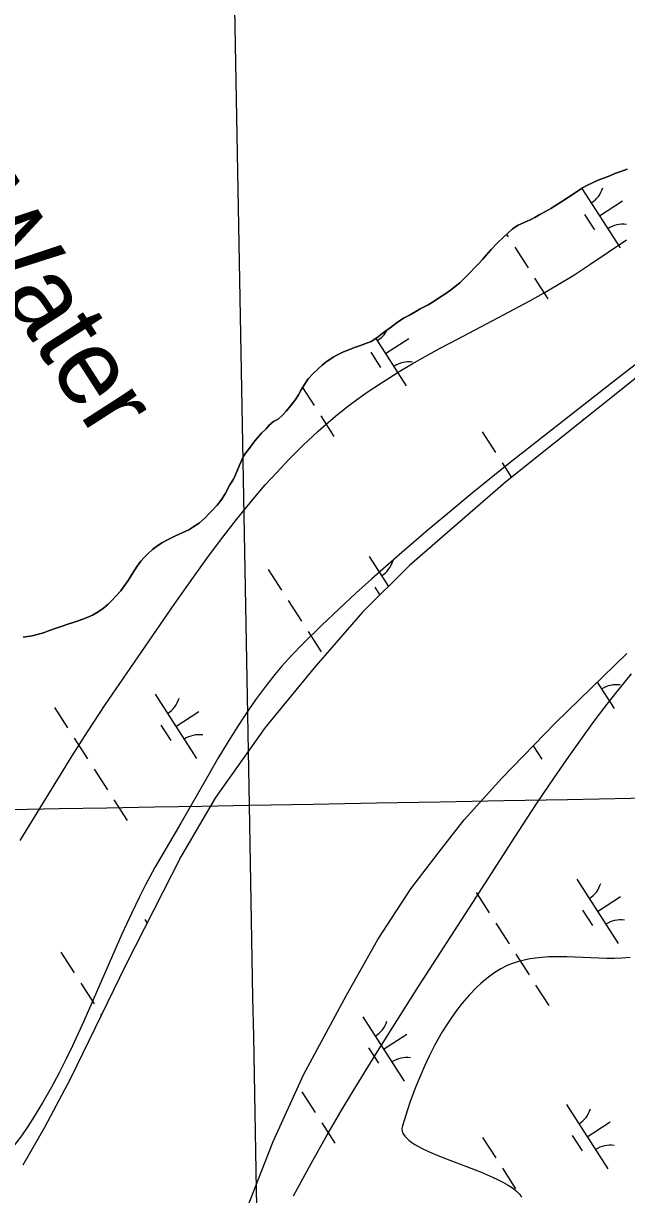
# Model space of a CAD drawing. Extents: x 3937982 to 3958556, y 219448 to 241894.
# Drawn here: x 3945931 to 3946325, y 230060 to 230826 of the extents above; entities that cross this region are included whole.
import ezdxf

# ---------------------------------------------------------------- set-up
doc = ezdxf.new("R2010")
doc.units = 0
for name, color, linetype in [('V-GRID-MAJR', 7, 'Continuous'), ('V-RIVR-IDEN', 7, 'Continuous'), ('V-SITE-VEGE', 7, 'Continuous'), ('V-TOPO-SHOR', 7, 'Continuous'), ('V-WETL-SWMP', 7, 'Continuous')]:
    doc.layers.add(name, color=color, linetype=linetype)

msp = doc.modelspace()

# ---------------------------------------------------------------- linework, layer by layer
at = {"layer": 'V-GRID-MAJR'}
for points in [[(3946136.867, 227095.12), (3946078.329, 230314.506), (3945968.142, 236374.431), (3945930.73, 238431.955)], [(3944087.88, 230278.368), (3946078.329, 230314.506), (3951399.696, 230411.652), (3955204.154, 230481.575)]]:
    msp.add_spline(points, degree=3, dxfattribs=at)
at = {"layer": 'V-SITE-VEGE'}
for p, q in [((3946316.959, 230386.607), (3946328.088, 230400.386)), ((3946310.758, 230378.632), (3946316.959, 230386.607)), ((3946303.803, 230369.436), (3946310.758, 230378.632)), ((3946296.004, 230358.826), (3946303.803, 230369.436)), ((3946287.274, 230346.583), (3946296.004, 230358.826)), ((3946277.496, 230332.449), (3946287.274, 230346.583)), ((3946266.54, 230316.145), (3946277.496, 230332.449)), ((3946254.223, 230297.351), (3946266.54, 230316.145)), ((3946224.457, 230250.88), (3946254.223, 230297.351)), ((3946188.933, 230195.922), (3946224.457, 230250.88)), ((3946246.822, 230209.629), (3946242.674, 230207.552)), ((3946249.654, 230210.798), (3946246.822, 230209.629)), ((3946253.504, 230212.113), (3946249.654, 230210.798)), ((3946258.759, 230213.467), (3946253.504, 230212.113)), ((3946261.819, 230214.057), (3946258.759, 230213.467)), ((3946265.354, 230214.581), (3946261.819, 230214.057)), ((3946269.442, 230215.011), (3946265.354, 230214.581)), ((3946274.164, 230215.3), (3946269.442, 230215.011)), ((3946279.61, 230215.421), (3946274.164, 230215.3)), ((3946285.871, 230215.347), (3946279.61, 230215.421)), ((3946311.891, 230214.327), (3946285.871, 230215.347)), ((3946316.771, 230214.319), (3946311.891, 230214.327)), ((3946321.879, 230214.491), (3946316.771, 230214.319)), ((3946327.185, 230214.939), (3946321.879, 230214.491)), ((3946232.4, 230200.321), (3946229.549, 230197.861)), ((3946235.433, 230202.727), (3946232.4, 230200.321)), ((3946238.66, 230205.06), (3946235.433, 230202.727)), ((3946242.674, 230207.552), (3946238.66, 230205.06)), ((3946171.986, 230169.435), (3946188.933, 230195.922)), ((3946226.866, 230195.373), (3946221.891, 230190.263)), ((3946229.549, 230197.861), (3946226.866, 230195.373)), ((3946217.492, 230185.172), (3946213.595, 230180.181)), ((3946221.891, 230190.263), (3946217.492, 230185.172)), ((3946213.595, 230180.181), (3946210.132, 230175.335)), ((3946207.053, 230170.682), (3946204.311, 230166.242)), ((3946210.132, 230175.335), (3946207.053, 230170.682)), ((3946160.869, 230151.732), (3946171.986, 230169.435)), ((3946204.311, 230166.242), (3946199.539, 230157.792)), ((3946199.539, 230157.792), (3946195.748, 230150.352)), ((3946146.31, 230127.983), (3946160.869, 230151.732)), ((3946195.748, 230150.352), (3946192.715, 230143.882)), ((3946192.715, 230143.882), (3946190.272, 230138.303)), ((3946190.272, 230138.303), (3946186.684, 230129.431)), ((3946138.134, 230114.301), (3946146.31, 230127.983)), ((3946186.684, 230129.431), (3946183.243, 230120.078)), ((3946183.243, 230120.078), (3946181.814, 230115.912)), ((3946128.93, 230098.527), (3946138.134, 230114.301)), ((3946181.814, 230115.912), (3946178.31, 230104.923)), ((3946178.099, 230103.999), (3946178.021, 230103.104)), ((3946178.021, 230103.104), (3946178.236, 230101.376)), ((3946178.31, 230104.923), (3946178.099, 230103.999)), ((3946178.236, 230101.376), (3946178.883, 230099.739)), ((3946118.609, 230080.287), (3946128.93, 230098.527)), ((3946178.883, 230099.739), (3946179.897, 230098.191)), ((3946179.897, 230098.191), (3946181.212, 230096.721)), ((3946181.212, 230096.721), (3946182.779, 230095.324)), ((3946182.779, 230095.324), (3946184.552, 230093.991)), ((3946184.552, 230093.991), (3946186.489, 230092.719)), ((3946186.489, 230092.719), (3946190.725, 230090.339)), ((3946190.725, 230090.339), (3946195.32, 230088.117)), ((3946195.32, 230088.117), (3946200.031, 230086.067)), ((3946200.031, 230086.067), (3946204.719, 230084.158)), ((3946107.084, 230059.105), (3946118.609, 230080.287)), ((3946204.719, 230084.158), (3946229.313, 230074.735)), ((3946229.313, 230074.735), (3946235.244, 230072.276)), ((3946235.244, 230072.276), (3946240.1, 230070.078)), ((3946240.1, 230070.078), (3946244.016, 230068.112)), ((3946244.016, 230068.112), (3946247.135, 230066.357)), ((3946247.135, 230066.357), (3946249.59, 230064.786)), ((3946249.59, 230064.786), (3946251.509, 230063.385)), ((3946251.509, 230063.385), (3946252.994, 230062.136)), ((3946252.994, 230062.136), (3946255.005, 230060.035)), ((3946255.005, 230060.035), (3946256.22, 230058.269))]:
    msp.add_line(p, q, dxfattribs=at)
for points in [[(3945928.48, 230291.467), (3945962.41, 230346.73), (3945972.347, 230362.365), (3945984.051, 230380.055), (3946029.609, 230446.302), (3946042.812, 230465.133), (3946050.492, 230475.785), (3946059.44, 230487.823), (3946069.932, 230501.366), (3946075.664, 230508.481), (3946081.896, 230515.975), (3946088.693, 230523.849), (3946096.124, 230532.105), (3946104.277, 230540.729), (3946113.253, 230549.707), (3946123.171, 230559.007), (3946128.441, 230563.689), (3946135.783, 230569.868), (3946143.295, 230575.766), (3946148.391, 230579.553), (3946155.28, 230584.44), (3946164.629, 230590.688), (3946177.337, 230598.61), (3946184.704, 230602.96), (3946193.201, 230607.799), (3946202.992, 230613.195), (3946214.26, 230619.233), (3946244.452, 230635.082), (3946261.602, 230644.305), (3946270.66, 230649.365), (3946280.231, 230654.917), (3946290.307, 230661.057), (3946300.874, 230667.908), (3946324.951, 230684.107)], [(3946375, 230636.678), (3946320.033, 230594.235), (3946283.78, 230566.071), (3946247.792, 230537.704), (3946224.025, 230518.537), (3946210.541, 230507.449), (3946195.234, 230494.635), (3946177.886, 230479.77), (3946158.272, 230462.45), (3946147.915, 230453.05), (3946136.95, 230442.89), (3946125.357, 230431.884), (3946113.112, 230419.94), (3946106.036, 230412.633), (3946099.292, 230405.082), (3946094.968, 230399.923), (3946089.396, 230392.9), (3946082.283, 230383.307), (3946078.361, 230377.723), (3946073.997, 230371.255), (3946069.139, 230363.772), (3946063.739, 230355.111), (3946057.719, 230345.104), (3946050.994, 230333.57), (3946033.338, 230302.655), (3946016.512, 230273.854), (3946010.349, 230262.359), (3946006.423, 230254.609), (3946001.381, 230244.187), (3945994.926, 230230.16), (3945970.096, 230173.394), (3945962.649, 230157.249), (3945958.502, 230148.699), (3945953.912, 230139.634)], [(3945953.912, 230139.634), (3945948.79, 230130.052), (3945943.033, 230119.933), (3945936.509, 230109.285), (3945932.968, 230103.856), (3945929.183, 230098.3), (3945925.593, 230093.468), (3945921.779, 230088.924), (3945919.119, 230086.042), (3945915.431, 230082.374), (3945910.278, 230077.768), (3945907.218, 230075.272), (3945903.628, 230072.526), (3945899.405, 230069.519), (3945894.432, 230066.238), (3945888.577, 230062.662), (3945881.682, 230058.765)]]:
    msp.add_lwpolyline(points, dxfattribs=at)
at = {"layer": 'V-TOPO-SHOR'}
for p, q in [((3946278.387, 230368.457), (3946325.008, 230413.677)), ((3946243.329, 230332.21), (3946278.387, 230368.457)), ((3946218.668, 230304.926), (3946243.329, 230332.21)), ((3946203.944, 230285.899), (3946218.668, 230304.926)), ((3946183.932, 230259.826), (3946203.944, 230285.899)), ((3946162.359, 230226.746), (3946183.932, 230259.826)), ((3946141.751, 230190.413), (3946162.359, 230226.746)), ((3946113.613, 230138.155), (3946141.751, 230190.413)), ((3946093.778, 230094.605), (3946113.613, 230138.155)), ((3946069.925, 230033.534), (3946093.778, 230094.605))]:
    msp.add_line(p, q, dxfattribs=at)
for points in [[(3946655.328, 230838.166), (3946632.511, 230813.236), (3946613.334, 230797.196), (3946587.893, 230778.299), (3946515.953, 230726.542), (3946438.459, 230670.767), (3946338.748, 230600.088), (3946245.832, 230525.75), (3946183.006, 230471.29), (3946152.325, 230440.688), (3946120.538, 230404.25), (3946088.546, 230365.246), (3946056.155, 230319.482), (3946033.707, 230281.274), (3945997.377, 230210.071), (3945961.087, 230135.375), (3945944.397, 230103.749), (3945930.199, 230079.141)], [(3946325.301, 230730.316), (3946321.059, 230728.801), (3946317.31, 230727.453), (3946313.887, 230725.944), (3946310.463, 230724.601), (3946306.222, 230723.085), (3946302.963, 230721.578), (3946298.892, 230719.573), (3946296.123, 230718.072), (3946291.247, 230714.911), (3946285.717, 230711.256), (3946280.19, 230707.598), (3946275.471, 230704.604), (3946272.381, 230702.773), (3946268.147, 230700.6), (3946264.891, 230698.767), (3946261.796, 230697.264), (3946257.887, 230695.423), (3946253.975, 230693.747), (3946250.399, 230691.255), (3946246.992, 230688.273), (3946244.397, 230685.957), (3946240.346, 230681.988), (3946236.295, 230677.855), (3946233.385, 230674.224), (3946230.796, 230671.25), (3946228.529, 230668.772), (3946225.287, 230665.628), (3946222.86, 230662.986), (3946219.133, 230659.183), (3946215.891, 230656.04), (3946212.806, 230653.553), (3946209.72, 230651.231), (3946205.98, 230648.575), (3946202.566, 230646.412), (3946198.337, 230643.586), (3946195.085, 230641.589), (3946189.875, 230638.916), (3946187.108, 230637.251), (3946183.039, 230634.919), (3946179.457, 230633.082), (3946175.879, 230630.755), (3946173.116, 230628.762), (3946170.355, 230626.608), (3946167.593, 230624.613), (3946164.832, 230622.622), (3946161.582, 230620.134), (3946158.006, 230617.642), (3946153.767, 230616.126), (3946150.832, 230614.951), (3946147.078, 230613.767), (3946143.33, 230612.255), (3946139.906, 230610.912), (3946135.832, 230608.907), (3946133.065, 230607.406), (3946128.353, 230604.084), (3946125.916, 230602.257), (3946123.157, 230599.775), (3946120.079, 230596.633), (3946116.675, 230593.326), (3946114.259, 230589.537), (3946112.166, 230586.078), (3946110.398, 230582.787), (3946108.467, 230579.655), (3946106.527, 230577.181), (3946104.588, 230574.705), (3946102.323, 230572.065), (3946099.892, 230569.585), (3946097.137, 230566.937), (3946094.043, 230565.432), (3946091.284, 230562.95), (3946089.181, 230560.638), (3946086.262, 230557.826), (3946083.35, 230554.358), (3946081.249, 230551.88), (3946078.341, 230547.924), (3946075.918, 230544.788), (3946074.144, 230542.152), (3946071.742, 230536.725), (3946069.188, 230530.481), (3946067.906, 230527.683), (3946065.488, 230524.058)], [(3946065.488, 230524.058), (3946062.438, 230518.136), (3946059.536, 230513.685), (3946057.111, 230510.716), (3946053.871, 230507.244), (3946051.768, 230504.932), (3946049.501, 230502.618), (3946045.444, 230498.974), (3946041.378, 230496.314), (3946038.616, 230494.485), (3946035.193, 230492.978), (3946032.261, 230491.638), (3946029.492, 230490.301), (3946025.255, 230488.294), (3946021.511, 230486.291), (3946018.42, 230484.296), (3946014.847, 230481.642), (3946012.09, 230478.994), (3946009.497, 230476.35), (3946007.23, 230474.036), (3946004.807, 230470.737), (3946001.426, 230465.301), (3945999.009, 230461.512), (3945996.265, 230457.556), (3945994.168, 230454.588), (3945991.256, 230451.285), (3945988.825, 230448.805), (3945985.908, 230445.829), (3945982.988, 230443.345), (3945979.41, 230441.016), (3945975.666, 230438.849), (3945972.246, 230437.178), (3945969.311, 230436.166), (3945966.213, 230434.989), (3945962.948, 230433.975), (3945959.522, 230432.957), (3945955.77, 230431.61), (3945951.856, 230430.262), (3945946.964, 230428.411), (3945943.701, 230427.233), (3945940.439, 230426.217), (3945936.193, 230425.191), (3945930.309, 230424.315)]]:
    msp.add_lwpolyline(points, dxfattribs=at)
at = {"layer": 'V-WETL-SWMP'}
for p, q in [((3946317.309, 230727.453), (3946321.06, 230728.8)), ((3946321.06, 230728.8), (3946325.301, 230730.316)), ((3946298.892, 230719.573), (3946302.964, 230721.578)), ((3946302.964, 230721.578), (3946306.222, 230723.085)), ((3946306.222, 230723.085), (3946310.463, 230724.601)), ((3946310.463, 230724.601), (3946313.887, 230725.945)), ((3946313.887, 230725.945), (3946317.309, 230727.453)), ((3946285.717, 230711.255), (3946291.246, 230714.912)), ((3946291.246, 230714.912), (3946296.124, 230718.072)), ((3946295.65, 230717.765), (3946320.729, 230678.803)), ((3946296.124, 230718.072), (3946298.892, 230719.573)), ((3946275.472, 230704.604), (3946280.189, 230707.598)), ((3946280.189, 230707.598), (3946285.717, 230711.255)), ((3946307.198, 230699.824), (3946322.334, 230709.567)), ((3946261.797, 230697.263), (3946264.892, 230698.768)), ((3946264.892, 230698.768), (3946268.147, 230700.601)), ((3946268.147, 230700.601), (3946272.381, 230702.772)), ((3946272.381, 230702.772), (3946275.472, 230704.604)), ((3946297.463, 230700.694), (3946303.958, 230690.603)), ((3946246.992, 230688.274), (3946250.4, 230691.255)), ((3946250.4, 230691.255), (3946253.975, 230693.747)), ((3946253.975, 230693.747), (3946257.887, 230695.423)), ((3946257.887, 230695.423), (3946261.797, 230697.263)), ((3946240.345, 230681.987), (3946244.397, 230685.956)), ((3946244.397, 230685.956), (3946246.992, 230688.274)), ((3946246.358, 230687.708), (3946247.461, 230685.995)), ((3946233.385, 230674.223), (3946236.294, 230677.854)), ((3946236.294, 230677.854), (3946240.345, 230681.987)), ((3946251.791, 230679.268), (3946260.451, 230665.814)), ((3946225.287, 230665.629), (3946228.529, 230668.772)), ((3946228.529, 230668.772), (3946230.796, 230671.25)), ((3946230.796, 230671.25), (3946233.385, 230674.223)), ((3946219.132, 230659.183), (3946222.859, 230662.986)), ((3946222.859, 230662.986), (3946225.287, 230665.629)), ((3946209.719, 230651.231), (3946212.806, 230653.554)), ((3946212.806, 230653.554), (3946215.89, 230656.04)), ((3946215.89, 230656.04), (3946219.132, 230659.183)), ((3946264.781, 230659.087), (3946273.441, 230645.634)), ((3946198.338, 230643.586), (3946202.566, 230646.411)), ((3946202.566, 230646.411), (3946205.981, 230648.574)), ((3946205.981, 230648.574), (3946209.719, 230651.231)), ((3946183.039, 230634.919), (3946187.108, 230637.252)), ((3946187.108, 230637.252), (3946189.874, 230638.917)), ((3946189.874, 230638.917), (3946195.085, 230641.589)), ((3946195.085, 230641.589), (3946198.338, 230643.586)), ((3946173.117, 230628.762), (3946175.879, 230630.755)), ((3946175.879, 230630.755), (3946179.457, 230633.082)), ((3946179.457, 230633.082), (3946183.039, 230634.919)), ((3946161.582, 230620.134), (3946164.831, 230622.622)), ((3946164.831, 230622.622), (3946167.593, 230624.614)), ((3946167.593, 230624.614), (3946170.356, 230626.607)), ((3946170.356, 230626.607), (3946173.117, 230628.762)), ((3946143.329, 230612.256), (3946147.078, 230613.767)), ((3946147.078, 230613.767), (3946150.831, 230614.951)), ((3946150.831, 230614.951), (3946153.766, 230616.126)), ((3946153.766, 230616.126), (3946158.006, 230617.642)), ((3946158.006, 230617.642), (3946161.582, 230620.134)), ((3946160.956, 230619.698), (3946180.862, 230588.773)), ((3946167.331, 230609.795), (3946182.467, 230619.537)), ((3946128.352, 230604.083), (3946133.066, 230607.405)), ((3946133.066, 230607.405), (3946135.833, 230608.906)), ((3946135.833, 230608.906), (3946139.905, 230610.912)), ((3946139.905, 230610.912), (3946143.329, 230612.256)), ((3946157.596, 230610.664), (3946164.091, 230600.574)), ((3946120.08, 230596.634), (3946123.158, 230599.775)), ((3946123.158, 230599.775), (3946125.915, 230602.258)), ((3946125.915, 230602.258), (3946128.352, 230604.083)), ((3946338.749, 230600.089), (3946245.832, 230525.75)), ((3946114.259, 230589.536), (3946116.676, 230593.326)), ((3946116.676, 230593.326), (3946120.08, 230596.634)), ((3946110.399, 230582.786), (3946112.166, 230586.078)), ((3946112.166, 230586.078), (3946114.259, 230589.536)), ((3946113.034, 230587.513), (3946120.584, 230575.785)), ((3946104.588, 230574.706), (3946108.466, 230579.656)), ((3946108.466, 230579.656), (3946110.399, 230582.786)), ((3946097.137, 230566.938), (3946099.892, 230569.585)), ((3946099.892, 230569.585), (3946102.323, 230572.065)), ((3946102.323, 230572.065), (3946104.588, 230574.706)), ((3946124.914, 230569.058), (3946133.574, 230555.604)), ((3946086.262, 230557.825), (3946089.18, 230560.637)), ((3946089.18, 230560.637), (3946091.284, 230562.95)), ((3946091.284, 230562.95), (3946094.042, 230565.433)), ((3946094.042, 230565.433), (3946097.137, 230566.938)), ((3946296.366, 230567.126), (3946296.768, 230566.502)), ((3946081.248, 230551.881), (3946083.35, 230554.358)), ((3946083.35, 230554.358), (3946086.262, 230557.825)), ((3946230.501, 230558.531), (3946239.161, 230545.077)), ((3946075.918, 230544.789), (3946078.341, 230547.923)), ((3946078.341, 230547.923), (3946081.248, 230551.881)), ((3946071.743, 230536.726), (3946074.144, 230542.152)), ((3946074.144, 230542.152), (3946075.918, 230544.789)), ((3946243.491, 230538.351), (3946249.64, 230528.797)), ((3946067.906, 230527.684), (3946069.188, 230530.48)), ((3946069.188, 230530.48), (3946071.743, 230536.726)), ((3946062.438, 230518.135), (3946065.488, 230524.058)), ((3946065.488, 230524.058), (3946067.906, 230527.684)), ((3946245.832, 230525.75), (3946183.005, 230471.29)), ((3946059.536, 230513.686), (3946062.438, 230518.135)), ((3946051.768, 230504.932), (3946053.872, 230507.245)), ((3946053.872, 230507.245), (3946057.111, 230510.715)), ((3946057.111, 230510.715), (3946059.536, 230513.686)), ((3946041.379, 230496.315), (3946045.444, 230498.975)), ((3946045.444, 230498.975), (3946049.5, 230502.617)), ((3946049.5, 230502.617), (3946051.768, 230504.932)), ((3946029.491, 230490.302), (3946032.26, 230491.639)), ((3946032.26, 230491.639), (3946035.193, 230492.978)), ((3946035.193, 230492.978), (3946038.615, 230494.486)), ((3946038.615, 230494.486), (3946041.379, 230496.315)), ((3946014.847, 230481.642), (3946018.421, 230484.297)), ((3946018.421, 230484.297), (3946021.511, 230486.292)), ((3946021.511, 230486.292), (3946025.255, 230488.295)), ((3946025.255, 230488.295), (3946029.491, 230490.302)), ((3946007.23, 230474.035), (3946009.498, 230476.35)), ((3946009.498, 230476.35), (3946012.091, 230478.995)), ((3946012.091, 230478.995), (3946014.847, 230481.642)), ((3946156.498, 230477.097), (3946169.139, 230457.459)), ((3946001.426, 230465.301), (3946004.808, 230470.737)), ((3946004.808, 230470.737), (3946007.23, 230474.035)), ((3946090.633, 230468.502), (3946099.293, 230455.048)), ((3946183.005, 230471.29), (3946152.324, 230440.688)), ((3945996.266, 230457.555), (3945999.009, 230461.512)), ((3945999.009, 230461.512), (3946001.426, 230465.301)), ((3945991.255, 230451.284), (3945994.168, 230454.588)), ((3945994.168, 230454.588), (3945996.266, 230457.555)), ((3946160.294, 230456.944), (3946163.551, 230451.886)), ((3945982.988, 230443.344), (3945985.909, 230445.829)), ((3945985.909, 230445.829), (3945988.825, 230448.804)), ((3945988.825, 230448.804), (3945991.255, 230451.284)), ((3946103.623, 230448.321), (3946112.283, 230434.867)), ((3945972.247, 230437.178), (3945975.667, 230438.85)), ((3945975.667, 230438.85), (3945979.41, 230441.016)), ((3945979.41, 230441.016), (3945982.988, 230443.344)), ((3946152.324, 230440.688), (3946120.538, 230404.25)), ((3945946.964, 230428.411), (3945951.856, 230430.261)), ((3945951.856, 230430.261), (3945955.771, 230431.61)), ((3945955.771, 230431.61), (3945959.522, 230432.957)), ((3945959.522, 230432.957), (3945962.949, 230433.974)), ((3945962.949, 230433.974), (3945966.212, 230434.989)), ((3945966.212, 230434.989), (3945969.311, 230436.167)), ((3945969.311, 230436.167), (3945972.247, 230437.178)), ((3945930.309, 230424.314), (3945936.193, 230425.192)), ((3945936.193, 230425.192), (3945940.439, 230426.217)), ((3945940.439, 230426.217), (3945943.702, 230427.232)), ((3945943.702, 230427.232), (3945946.964, 230428.411)), ((3946116.613, 230428.14), (3946125.273, 230414.686)), ((3946278.387, 230368.456), (3946325.008, 230413.676)), ((3946120.538, 230404.25), (3946088.545, 230365.247)), ((3946305.653, 230394.902), (3946316.69, 230377.755)), ((3946016.631, 230387.067), (3946043.694, 230345.024)), ((3945950.766, 230378.472), (3945959.426, 230365.018)), ((3946030.162, 230366.046), (3946045.298, 230375.788)), ((3946020.427, 230366.915), (3946026.922, 230356.824)), ((3946088.545, 230365.247), (3946056.154, 230319.482)), ((3946243.329, 230332.209), (3946278.387, 230368.456)), ((3945963.756, 230358.292), (3945972.416, 230344.838)), ((3946263.767, 230353.34), (3946269.401, 230344.586)), ((3945976.746, 230338.111), (3945985.406, 230324.657)), ((3946218.668, 230304.925), (3946243.329, 230332.209)), ((3945989.736, 230317.93), (3945998.396, 230304.476)), ((3946056.154, 230319.482), (3946033.706, 230281.275)), ((3946203.944, 230285.898), (3946218.668, 230304.925)), ((3946183.932, 230259.825), (3946203.944, 230285.898)), ((3946033.706, 230281.275), (3945997.378, 230210.072)), ((3946292.326, 230266.078), (3946319.389, 230224.035)), ((3946162.359, 230226.745), (3946183.932, 230259.825)), ((3946226.461, 230257.484), (3946235.121, 230244.03)), ((3946305.857, 230245.057), (3946320.993, 230254.799)), ((3946009.893, 230239.739), (3946011.355, 230237.468)), ((3946296.122, 230245.926), (3946302.617, 230235.836)), ((3946239.451, 230237.303), (3946248.111, 230223.849)), ((3946141.751, 230190.412), (3946162.359, 230226.745)), ((3945955.027, 230218.342), (3945963.687, 230204.888)), ((3946252.441, 230217.122), (3946261.101, 230203.668)), ((3945997.378, 230210.072), (3945961.086, 230135.375)), ((3945968.017, 230198.161), (3945976.677, 230184.707)), ((3946265.431, 230196.941), (3946274.091, 230183.487)), ((3946113.613, 230138.154), (3946141.751, 230190.412)), ((3945981.007, 230177.981), (3945981.451, 230177.291)), ((3946152.459, 230176.049), (3946179.521, 230134.006)), ((3946165.99, 230155.027), (3946181.126, 230164.77)), ((3946156.255, 230155.897), (3946162.75, 230145.806)), ((3945961.086, 230135.375), (3945944.397, 230103.75)), ((3946093.778, 230094.604), (3946113.613, 230138.154)), ((3946112.574, 230127.093), (3946121.234, 230113.639)), ((3946285.588, 230118.75), (3946312.651, 230076.707)), ((3945944.397, 230103.75), (3945930.199, 230079.141)), ((3946125.564, 230106.912), (3946134.224, 230093.458)), ((3946299.119, 230097.729), (3946314.255, 230107.471)), ((3946069.925, 230033.533), (3946093.778, 230094.604)), ((3946230.722, 230097.353), (3946239.382, 230083.899)), ((3946289.384, 230098.598), (3946295.879, 230088.508)), ((3946243.712, 230077.173), (3946252.372, 230063.719))]:
    msp.add_line(p, q, dxfattribs=at)
for centre, start, end in [((3946292.448, 230723.179), 301.99668, 343.540338), ((3946322.348, 230676.727), 81.996677, 123.540335), ((3946152.581, 230633.149), 301.99668, 332.787168), ((3946182.481, 230586.697), 81.996677, 123.540335), ((3946155.279, 230479.43), 301.99668, 343.540338), ((3946318.309, 230375.679), 81.996677, 123.540335), ((3946015.412, 230389.4), 301.99668, 343.540338), ((3946045.312, 230342.948), 81.996677, 123.540335), ((3946291.107, 230268.411), 301.99668, 343.540338), ((3946321.007, 230221.959), 81.996677, 123.540335), ((3946151.24, 230178.382), 301.99668, 343.540338), ((3946181.14, 230131.93), 81.996677, 123.540335), ((3946284.369, 230121.083), 301.99668, 343.540338), ((3946314.269, 230074.631), 81.996677, 123.540335)]:
    msp.add_arc(centre, 17.623, start, end, dxfattribs=at)

# ---------------------------------------------------------------- texts
at = {"layer": 'V-RIVR-IDEN'}
msp.add_text('Water', height=49.9999, rotation=302.768556, dxfattribs=at).set_placement((3945882.433, 230701.191))

doc.saveas('drawing.dxf')
